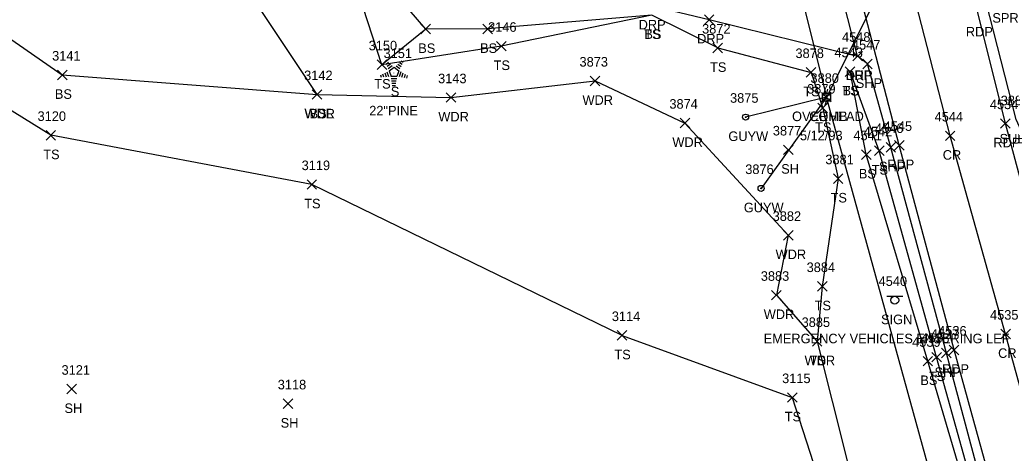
# Model space of a CAD drawing. Extents: x 1601151 to 1602912, y 499508 to 501770.
# Drawn here: x 1601482.2 to 1601689.5, y 500250.6 to 500341.3 of the extents above; entities that cross this region are included whole.
import ezdxf

# ---------------------------------------------------------------- set-up
doc = ezdxf.new("R2010")
doc.units = 0
for name, color, linetype in [('L_A', 7, 'Continuous'), ('L_C', 7, 'Continuous'), ('L_I', 7, 'Continuous'), ('L_TIC', 7, 'Continuous'), ('LAWA', 7, 'Continuous'), ('LELB', 7, 'Continuous'), ('LTC', 7, 'Continuous'), ('P_A', 7, 'Continuous'), ('P_I', 7, 'Continuous'), ('P_TIC', 7, 'Continuous'), ('PET', 7, 'Continuous'), ('PRC', 7, 'Continuous'), ('PSP', 7, 'Continuous'), ('R_A', 7, 'Continuous'), ('R_I', 7, 'Continuous'), ('R_TIC', 7, 'Continuous'), ('RDP', 7, 'Continuous'), ('S_A', 7, 'Continuous'), ('S_C', 7, 'Continuous'), ('S_I', 7, 'Continuous'), ('SSGN', 7, 'Continuous'), ('U_A', 7, 'Continuous'), ('U_C', 7, 'Continuous'), ('U_I', 7, 'Continuous'), ('U_TIC', 7, 'Continuous'), ('UCO', 7, 'Continuous'), ('UP', 7, 'Continuous'), ('UPGW', 7, 'Continuous'), ('UT', 7, 'Continuous')]:
    doc.layers.add(name, color=color, linetype=linetype)

msp = doc.modelspace()

# ---------------------------------------------------------------- linework, layer by layer
at = {"layer": 'L_TIC'}
for points in [[(1601566.07, 500338.35), (1601568.07, 500340.35)], [(1601568.07, 500338.35), (1601566.07, 500340.35)], [(1601579.01, 500338.37), (1601581.01, 500340.37)], [(1601581.01, 500338.37), (1601579.01, 500340.37)], [(1601581.87, 500334.78), (1601583.87, 500336.78)], [(1601583.87, 500334.78), (1601581.87, 500336.78)], [(1601627.14, 500334.4), (1601629.14, 500336.4)], [(1601629.14, 500334.4), (1601627.14, 500336.4)], [(1601556.91, 500330.9), (1601558.91, 500332.9)], [(1601558.91, 500330.9), (1601556.91, 500332.9)], [(1601646.67, 500329.29), (1601648.67, 500331.29)], [(1601648.67, 500329.29), (1601646.67, 500331.29)], [(1601654.82, 500329.46), (1601656.82, 500331.46)], [(1601656.82, 500329.46), (1601654.82, 500331.46)], [(1601654.82, 500329.46), (1601656.82, 500331.46)], [(1601656.82, 500329.46), (1601654.82, 500331.46)], [(1601490.06, 500328.76), (1601492.06, 500330.76)], [(1601492.06, 500328.76), (1601490.06, 500330.76)], [(1601601.5, 500327.5), (1601603.5, 500329.5)], [(1601603.5, 500327.5), (1601601.5, 500329.5)], [(1601543.34, 500324.67), (1601545.34, 500326.67)], [(1601545.34, 500324.67), (1601543.34, 500326.67)], [(1601543.34, 500324.67), (1601545.34, 500326.67)], [(1601545.34, 500324.67), (1601543.34, 500326.67)], [(1601543.34, 500324.67), (1601545.34, 500326.67)], [(1601545.34, 500324.67), (1601543.34, 500326.67)], [(1601571.35, 500324.03), (1601573.35, 500326.03)], [(1601573.35, 500324.03), (1601571.35, 500326.03)], [(1601649.11, 500321.84), (1601651.11, 500323.84)], [(1601651.11, 500321.84), (1601649.11, 500323.84)], [(1601620.3, 500318.7), (1601622.3, 500320.7)], [(1601622.3, 500318.7), (1601620.3, 500320.7)], [(1601487.66, 500316.14), (1601489.66, 500318.14)], [(1601489.66, 500316.14), (1601487.66, 500318.14)], [(1601641.94, 500313.1), (1601643.94, 500315.1)], [(1601643.94, 500313.1), (1601641.94, 500315.1)], [(1601660.95, 500312.91), (1601662.95, 500314.91)], [(1601662.95, 500312.91), (1601660.95, 500314.91)], [(1601658.22, 500312.1), (1601660.22, 500314.1)], [(1601660.22, 500312.1), (1601658.22, 500314.1)], [(1601652.35, 500307.08), (1601654.35, 500309.08)], [(1601654.35, 500307.08), (1601652.35, 500309.08)], [(1601542.25, 500305.85), (1601544.25, 500307.85)], [(1601544.25, 500305.85), (1601542.25, 500307.85)], [(1601641.9, 500295.23), (1601643.9, 500297.23)], [(1601643.9, 500295.23), (1601641.9, 500297.23)], [(1601649.01, 500284.53), (1601651.01, 500286.53)], [(1601651.01, 500284.53), (1601649.01, 500286.53)], [(1601639.42, 500282.7), (1601641.42, 500284.7)], [(1601641.42, 500282.7), (1601639.42, 500284.7)], [(1601607.13, 500274.28), (1601609.13, 500276.28)], [(1601609.13, 500274.28), (1601607.13, 500276.28)], [(1601607.13, 500274.28), (1601609.13, 500276.28)], [(1601609.13, 500274.28), (1601607.13, 500276.28)], [(1601647.96, 500273.04), (1601649.96, 500275.04)], [(1601649.96, 500273.04), (1601647.96, 500275.04)], [(1601647.96, 500273.04), (1601649.96, 500275.04)], [(1601649.96, 500273.04), (1601647.96, 500275.04)], [(1601672.93, 500269.73), (1601674.93, 500271.73)], [(1601674.93, 500269.73), (1601672.93, 500271.73)], [(1601671.09, 500268.9), (1601673.09, 500270.9)], [(1601673.09, 500268.9), (1601671.09, 500270.9)], [(1601492.02, 500263.05), (1601494.02, 500265.05)], [(1601494.02, 500263.05), (1601492.02, 500265.05)], [(1601642.75, 500261.3), (1601644.75, 500263.3)], [(1601644.75, 500261.3), (1601642.75, 500263.3)], [(1601537.25, 500259.99), (1601539.25, 500261.99)], [(1601539.25, 500259.99), (1601537.25, 500261.99)]]:
    msp.add_lwpolyline(points, dxfattribs=at)
at = {"layer": 'LAWA'}
for points in [[(1601544.34, 500325.67), (1601519.22, 500363.44), (1601505.75, 500400.34), (1601520.62, 500411.67), (1601500.1, 500494.02), (1601464.79, 500509.89), (1601431.61, 500509.7), (1601398.17, 500505.26), (1601396.59, 500512.31), (1601395.61, 500523.84), (1601392.91, 500532.17), (1601391.39, 500554.19), (1601400.22, 500561.71), (1601429.3, 500567.09), (1601477.41, 500577.92), (1601523.77, 500579.55), (1601560.2, 500571.77), (1601556.37, 500545), (1601575.25, 500522.25), (1601572.33, 500557.32), (1601570.48, 500566.05)], [(1601572.35, 500325.03), (1601602.5, 500328.5)], [(1601602.5, 500328.5), (1601621.3, 500319.7), (1601642.9, 500296.23), (1601640.42, 500283.7), (1601648.96, 500274.04), (1601661.48, 500224.09), (1601672.62, 500183.29)], [(1601544.34, 500325.67), (1601572.35, 500325.03)]]:
    msp.add_lwpolyline(points, dxfattribs=at)
at = {"layer": 'LELB'}
for points in [[(1601401.43, 500367.95), (1601438.99, 500365.98), (1601491.06, 500329.76), (1601544.34, 500325.67)], [(1601614.36, 500342.29), (1601582.87, 500335.78), (1601557.91, 500331.9), (1601550.18, 500355.75), (1601579.12, 500362.69)], [(1601614.36, 500342.29), (1601580.01, 500339.37), (1601567.07, 500339.35), (1601558.83, 500349.04), (1601579.12, 500362.69)], [(1601608.13, 500275.28), (1601543.25, 500306.85), (1601488.66, 500317.14), (1601446.35, 500343.38), (1601404.37, 500354.52)], [(1601628.14, 500335.4), (1601614.36, 500342.29)], [(1601567.07, 500339.35), (1601557.91, 500331.9)], [(1601628.14, 500335.4), (1601647.67, 500330.29), (1601650.11, 500322.84), (1601653.35, 500308.08), (1601650.01, 500285.53), (1601648.96, 500274.04)], [(1601817.31, 499872.7), (1601822.26, 499874.94), (1601824.19, 499882.19), (1601820.64, 499891.83), (1601797.18, 499933.64), (1601778.06, 499967.49), (1601759.63, 500004.16), (1601735.92, 500054.97), (1601725.84, 500087), (1601715.25, 500119.3), (1601698.06, 500177.62), (1601684.73, 500227.08), (1601672.09, 500269.9), (1601659.22, 500313.1), (1601655.82, 500330.46)], [(1601820.64, 499891.83), (1601799.69, 499935.32), (1601781.01, 499969.12), (1601762.54, 500005.3), (1601740.72, 500057.2), (1601729.05, 500088.56), (1601717.64, 500121.66), (1601699.62, 500177.82), (1601686.02, 500227.23), (1601673.93, 500270.73), (1601661.95, 500313.91), (1601655.82, 500330.46)], [(1601608.13, 500275.28), (1601643.75, 500262.3), (1601659.21, 500214.4)]]:
    msp.add_lwpolyline(points, dxfattribs=at)
at = {"layer": 'LTC'}
for p, q in [((1601558.58, 500332.5), (1601558.93, 500332.75)), ((1601558.78, 500332.03), (1601559.31, 500332.42)), ((1601558.99, 500331.57), (1601559.7, 500332.08)), ((1601559.2, 500331.1), (1601560.08, 500331.74)), ((1601559.43, 500330.65), (1601560.44, 500331.38)), ((1601560.44, 500331.38), (1601561.44, 500330.65)), ((1601560.86, 500331.69), (1601561.67, 500331.1)), ((1601561.23, 500332.04), (1601561.91, 500331.55)), ((1601561.6, 500332.39), (1601562.15, 500331.99)), ((1601561.97, 500332.74), (1601562.39, 500332.43)), ((1601557.61, 500329.78), (1601557.76, 500329.31)), ((1601558.06, 500329.99), (1601558.27, 500329.34)), ((1601558.52, 500330.21), (1601558.79, 500329.37)), ((1601558.97, 500330.43), (1601559.3, 500329.41)), ((1601559.43, 500330.65), (1601559.82, 500329.45)), ((1601561.05, 500329.45), (1601559.82, 500329.45)), ((1601561.44, 500330.65), (1601561.05, 500329.45)), ((1601561.87, 500330.38), (1601561.54, 500329.34)), ((1601562.32, 500330.13), (1601562.03, 500329.25)), ((1601562.76, 500329.88), (1601562.53, 500329.15)), ((1601563.21, 500329.63), (1601563.02, 500329.06)), ((1601561.01, 500328.95), (1601559.86, 500328.95)), ((1601560.92, 500328.45), (1601559.94, 500328.45)), ((1601560.84, 500327.95), (1601560.01, 500327.95)), ((1601560.76, 500327.45), (1601560.08, 500327.45))]:
    msp.add_line(p, q, dxfattribs=at)
at = {"layer": 'P_TIC'}
for points in [[(1601656.41, 500332.69), (1601658.41, 500334.69)], [(1601658.41, 500332.69), (1601656.41, 500334.69)], [(1601658.49, 500331.06), (1601660.49, 500333.06)], [(1601660.49, 500331.06), (1601658.49, 500333.06)], [(1601687.33, 500318.61), (1601689.33, 500320.61)], [(1601689.33, 500318.61), (1601687.33, 500320.61)], [(1601675.78, 500316.03), (1601677.78, 500318.03)], [(1601677.78, 500316.03), (1601675.78, 500318.03)], [(1601663.35, 500313.61), (1601665.35, 500315.61)], [(1601665.35, 500313.61), (1601663.35, 500315.61)], [(1601665.12, 500314.05), (1601667.12, 500316.05)], [(1601667.12, 500314.05), (1601665.12, 500316.05)], [(1601687.37, 500274.57), (1601689.37, 500276.57)], [(1601689.37, 500274.57), (1601687.37, 500276.57)], [(1601676.58, 500271.25), (1601678.58, 500273.25)], [(1601678.58, 500271.25), (1601676.58, 500273.25)], [(1601674.97, 500270.58), (1601676.97, 500272.58)], [(1601676.97, 500270.58), (1601674.97, 500272.58)]]:
    msp.add_lwpolyline(points, dxfattribs=at)
at = {"layer": 'PET'}
for points in [[(1601995.67, 499683.24), (1601967.44, 499723.89), (1601951.2, 499747.81), (1601928.38, 499780.82), (1601898.7, 499825.12), (1601866.23, 499874.79), (1601846.19, 499907.84), (1601823.76, 499946.63), (1601805.55, 499981.9), (1601788.87, 500017.29), (1601766.92, 500067.61), (1601755.39, 500098.81), (1601743.92, 500129.72), (1601726.45, 500185.71), (1601711.93, 500234.21), (1601699.42, 500278.31), (1601688.33, 500319.61), (1601682.56, 500342.8), (1601675.53, 500367.54), (1601665.76, 500404.47), (1601656.17, 500441.2), (1601643.95, 500489.36), (1601630.25, 500541.68)], [(1601976.03, 499671.31), (1601949.07, 499710.22), (1601932.5, 499734.59), (1601906.16, 499773.6), (1601879.17, 499813.54), (1601846.78, 499862.77), (1601825.9, 499896.89), (1601802.83, 499936.77), (1601785.08, 499971.15), (1601767.41, 500007.57), (1601745.41, 500058.72), (1601733.84, 500089.25), (1601721.8, 500122.71), (1601703.99, 500178.99), (1601689.71, 500228.27), (1601677.58, 500272.25), (1601666.12, 500315.05), (1601653.43, 500363.86), (1601644.59, 500397.8), (1601635.03, 500435.31), (1601622.92, 500483.99), (1601609.64, 500536.46)]]:
    msp.add_lwpolyline(points, dxfattribs=at)
at = {"layer": 'PRC'}
msp.add_lwpolyline([(1601985.39, 499677.47), (1601958.56, 499716.67), (1601942.32, 499739.6), (1601916.26, 499778.51), (1601888.68, 499819.15), (1601856.54, 499869.05), (1601836.01, 499902.11), (1601813.37, 499942.52), (1601794.98, 499977.03), (1601778.27, 500012.72), (1601755.57, 500062.85), (1601744.49, 500093.78), (1601732.77, 500126.07), (1601715.37, 500182.36), (1601700.57, 500231.28), (1601688.37, 500275.57), (1601676.78, 500317.03), (1601664.23, 500365.85), (1601655.24, 500401.01), (1601645.63, 500438.14), (1601632.99, 500486.74), (1601619.53, 500538.88)], dxfattribs=at)
at = {"layer": 'PSP'}
msp.add_lwpolyline([(1601687.75, 500227.8), (1601675.97, 500271.58), (1601664.35, 500314.61), (1601659.49, 500332.06), (1601657.41, 500333.69), (1601650.64, 500360.12), (1601651.12, 500363.17), (1601643.24, 500397.34), (1601633.67, 500434.79), (1601621.75, 500483.67), (1601608.78, 500536.08)], dxfattribs=at)
at = {"layer": 'R_TIC'}
for points in [[(1601625.36, 500340.34), (1601627.36, 500342.34)], [(1601627.36, 500340.34), (1601625.36, 500342.34)], [(1601656.41, 500332.69), (1601658.41, 500334.69)], [(1601658.41, 500332.69), (1601656.41, 500334.69)]]:
    msp.add_lwpolyline(points, dxfattribs=at)
at = {"layer": 'RDP'}
msp.add_lwpolyline([(1601614.12, 500344.28), (1601626.36, 500341.34), (1601657.41, 500333.69)], dxfattribs=at)
at = {"layer": 'SSGN'}
for p, q in [((1601663.52, 500283.49), (1601666.85, 500283.49)), ((1601665.17, 500282.65), (1601665.17, 500282.65))]:
    msp.add_line(p, q, dxfattribs=at)
msp.add_circle((1601665.17, 500282.65), 0.833, dxfattribs=at)
at = {"layer": 'U_TIC'}
for points in [[(1601649.89, 500324.1), (1601651.89, 500326.1)], [(1601651.89, 500324.1), (1601649.89, 500326.1)], [(1601649.89, 500324.1), (1601651.89, 500326.1)], [(1601651.89, 500324.1), (1601649.89, 500326.1)], [(1601649.89, 500324.1), (1601651.89, 500326.1)], [(1601651.89, 500324.1), (1601649.89, 500326.1)]]:
    msp.add_lwpolyline(points, dxfattribs=at)
at = {"layer": 'UCO'}
for points in [[(1601595.97, 500546.62), (1601650.89, 500325.1)], [(1601727.82, 500478.91), (1601650.89, 500325.1)], [(1601870.49, 499699.14), (1601777.6, 499915.52), (1601705.51, 500127.03), (1601650.89, 500325.1)]]:
    msp.add_lwpolyline(points, dxfattribs=at)
at = {"layer": 'UP'}
for p, q in [((1601650.06, 500324.27), (1601650.06, 500325.94)), ((1601650.06, 500325.94), (1601651.72, 500325.94)), ((1601651.14, 500326.77), (1601650.89, 500325.94)), ((1601650.89, 500325.1), (1601650.89, 500325.1)), ((1601651.72, 500325.94), (1601651.72, 500324.27)), ((1601651.72, 500324.27), (1601650.06, 500324.27)), ((1601650.64, 500323.44), (1601650.89, 500324.27))]:
    msp.add_line(p, q, dxfattribs=at)
msp.add_circle((1601650.89, 500325.1), 0.833, dxfattribs=at)
at = {"layer": 'UPGW'}
for points in [[(1601650.89, 500325.1), (1601633.99, 500320.94)], [(1601650.89, 500325.1), (1601637.22, 500306.03)]]:
    msp.add_lwpolyline(points, dxfattribs=at)
for centre, radius in [((1601633.99, 500320.94), 0.625), ((1601633.99, 500320.94), 0.0833), ((1601637.22, 500306.03), 0.625), ((1601637.22, 500306.03), 0.0833)]:
    msp.add_circle(centre, radius, dxfattribs=at)
at = {"layer": 'UT'}
msp.add_lwpolyline([(1601700.45, 500298.64), (1601690.61, 500320.42), (1601678.81, 500366.62)], dxfattribs=at)

# ---------------------------------------------------------------- texts
at = {"layer": 'L_A'}
for s, p in [('TS', (1601612.77, 500337.29)), ('BS', (1601612.8, 500337.29)), ('BS', (1601565.51, 500334.35)), ('BS', (1601578.45, 500334.37)), ('TS', (1601581.28, 500330.78)), ('TS', (1601626.55, 500330.4)), ('TS', (1601556.32, 500326.9)), ('S', (1601559.77, 500325.29)), ('TS', (1601646.08, 500325.29)), ('TS', (1601654.23, 500325.46)), ('BS', (1601654.26, 500325.46)), ('BS', (1601489.5, 500324.76)), ('WDR', (1601599.86, 500323.5)), ('WDR', (1601541.7, 500320.67)), ('WDL', (1601541.75, 500320.67)), ('BS', (1601542.78, 500320.67)), ('WDR', (1601569.71, 500320.03)), ('TS', (1601648.52, 500317.84)), ('WDR', (1601618.66, 500314.7)), ('TS', (1601487.07, 500312.14)), ('SH', (1601641.43, 500309.1)), ('TS', (1601660.36, 500308.91)), ('BS', (1601657.66, 500308.1)), ('TS', (1601651.76, 500303.08)), ('TS', (1601541.66, 500301.85)), ('WDR', (1601640.26, 500291.23)), ('TS', (1601648.42, 500280.53)), ('WDR', (1601637.78, 500278.7)), ('TS', (1601606.54, 500270.28)), ('TS', (1601606.54, 500270.28)), ('TS', (1601647.37, 500269.04)), ('WDR', (1601646.32, 500269.04)), ('BS', (1601670.53, 500264.9)), ('TS', (1601672.34, 500265.73)), ('SH', (1601491.51, 500259.05)), ('TS', (1601642.16, 500257.3)), ('SH', (1601536.73, 500255.99))]:
    msp.add_text(s, height=2, dxfattribs=at).set_placement(p)
at = {"layer": 'L_C'}
msp.add_text('22"PINE', height=2, dxfattribs=at).set_placement((1601555.26, 500321.29))
at = {"layer": 'L_I'}
for s, p in [('3146', (1601580.12, 500338.78)), ('3872', (1601624.88, 500338.4)), ('3150', (1601555.14, 500334.9)), ('3151', (1601558.25, 500333.29)), ('4543', (1601652.56, 500333.46)), ('4543', (1601652.56, 500333.46)), ('3141', (1601488.93, 500332.76)), ('3873', (1601599.24, 500331.5)), ('3878', (1601644.41, 500333.29)), ('3142', (1601541.64, 500328.67)), ('3142', (1601541.64, 500328.67)), ('3142', (1601541.64, 500328.67)), ('3143', (1601569.66, 500328.03)), ('3879', (1601646.85, 500325.84)), ('3874', (1601618.04, 500322.7)), ('3120', (1601485.88, 500320.14)), ('3877', (1601639.68, 500317.1)), ('4542', (1601658.69, 500316.91)), ('4541', (1601656.53, 500316.1)), ('3881', (1601650.66, 500311.08)), ('3119', (1601541.12, 500309.85)), ('3882', (1601639.64, 500299.23)), ('3884', (1601646.75, 500288.53)), ('3883', (1601637.16, 500286.7)), ('3114', (1601606, 500278.28)), ('3114', (1601606, 500278.28)), ('3885', (1601645.7, 500277.04)), ('3885', (1601645.7, 500277.04)), ('4538', (1601670.67, 500273.73)), ('4539', (1601668.82, 500272.9)), ('3121', (1601490.9, 500267.05)), ('3115', (1601641.62, 500265.3)), ('3118', (1601536.12, 500263.99))]:
    msp.add_text(s, height=2, dxfattribs=at).set_placement(p)
at = {"layer": 'LTC'}
msp.add_text('.', height=1.04, rotation=270, dxfattribs=at).set_placement((1601560.32, 500330.39))
at = {"layer": 'P_A'}
for s, p in [('RDP', (1601680.05, 500337.8)), ('SHP', (1601654.95, 500328.69)), ('SHP', (1601657.03, 500327.06)), ('RDP', (1601685.81, 500314.61)), ('CR', (1601675.22, 500312.03)), ('SHP', (1601661.89, 500309.61)), ('RDP', (1601663.61, 500310.05)), ('CR', (1601686.8, 500270.57)), ('RDP', (1601675.06, 500267.25)), ('SHP', (1601673.51, 500266.58))]:
    msp.add_text(s, height=2, dxfattribs=at).set_placement(p)
at = {"layer": 'P_I'}
for s, p in [('4548', (1601654.15, 500336.69)), ('4547', (1601656.23, 500335.06)), ('4534', (1601685.07, 500322.61)), ('4544', (1601673.52, 500320.03)), ('4546', (1601661.04, 500317.61)), ('4545', (1601662.86, 500318.05)), ('4535', (1601685.11, 500278.57)), ('4536', (1601674.26, 500275.25)), ('4537', (1601672.71, 500274.58))]:
    msp.add_text(s, height=2, dxfattribs=at).set_placement(p)
at = {"layer": 'R_A'}
for p in [(1601611.61, 500339.28), (1601623.84, 500336.34), (1601654.9, 500328.69)]:
    msp.add_text('DRP', height=2, dxfattribs=at).set_placement(p)
at = {"layer": 'R_I'}
msp.add_text('4548', height=2, dxfattribs=at).set_placement((1601654.15, 500336.69))
at = {"layer": 'S_A'}
msp.add_text('SIGN', height=2, dxfattribs=at).set_placement((1601662.31, 500277.63))
at = {"layer": 'S_C'}
for s, p in [('SPRING HOLLOW RD TH84', (1601685.6, 500340.69)), ('EMERGENCY VEHICLES ENTERING LEF', (1601637.76, 500273.63))]:
    msp.add_text(s, height=2, dxfattribs=at).set_placement(p)
at = {"layer": 'S_I'}
msp.add_text('4540', height=2, dxfattribs=at).set_placement((1601661.8, 500285.63))
at = {"layer": 'U_A'}
for s, p in [('OVERHEAD', (1601643.7, 500320.1)), ('OVERHEAD', (1601643.7, 500320.1)), ('OVERHEAD', (1601643.7, 500320.1)), ('COMB', (1601647.28, 500320.1)), ('GUYW', (1601630.38, 500315.94)), ('SUBT', (1601687.11, 500315.42)), ('GUYW', (1601633.61, 500301.03))]:
    msp.add_text(s, height=2, dxfattribs=at).set_placement(p)
at = {"layer": 'U_C'}
msp.add_text('5/12/93', height=2, dxfattribs=at).set_placement((1601645.35, 500316.1))
at = {"layer": 'U_I'}
for s, p in [('3880', (1601647.55, 500328.1)), ('3880', (1601647.55, 500328.1)), ('3880', (1601647.55, 500328.1)), ('3880', (1601647.55, 500328.1)), ('3875', (1601630.73, 500323.94)), ('3889', (1601687.34, 500323.42)), ('3876', (1601633.91, 500309.03))]:
    msp.add_text(s, height=2, dxfattribs=at).set_placement(p)

doc.saveas('drawing.dxf')
